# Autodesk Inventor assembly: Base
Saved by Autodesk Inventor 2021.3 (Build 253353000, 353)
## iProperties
Created: 2022-04
Part Number: Base
Document SubType Name: Assembly
Designer: Administrator
Title: Base v10
Author: Administrator
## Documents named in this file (2)
- c:\worker\convert-fusion-r02\tmp\job-1\1306\output\files\b05f09b4-aa40-4880-97ea-f63257dc7617\91c4d934-93ad-42b1-ae75-5b3f7740b66a.iam
- c:\worker\convert-fusion-r02\tmp\job-1\1306\output\files\b05f09b4-aa40-4880-97ea-f63257dc7617\Component4.ipt
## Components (1 placed, 1 different names)
1. Component4:1
